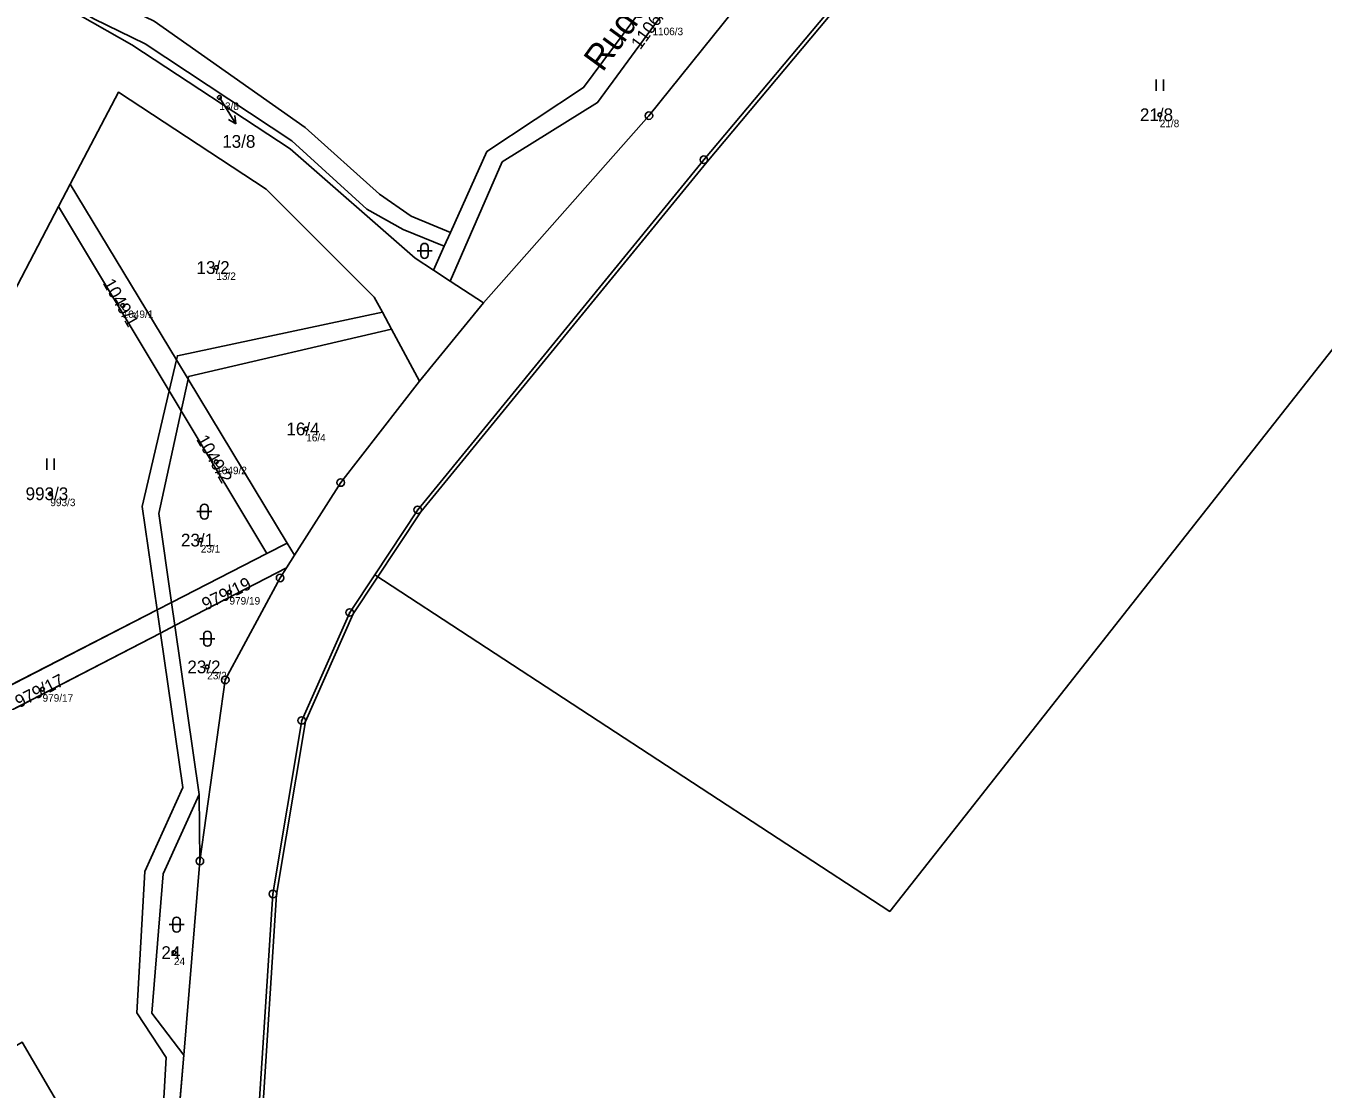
# Model space of a CAD drawing. Extents: x -554500 to -548272, y -1079733 to -1073730.
# Drawn here: x -553611.1 to -553438.1, y -1077094.1 to -1076952.3 of the extents above; entities that cross this region are included whole.
import ezdxf

# ---------------------------------------------------------------- set-up
doc = ezdxf.new("R2010")
doc.units = 0
for name, color, linetype in [('Definiční body', 7, 'Continuous'), ('Hranice parcel', 7, 'Continuous'), ('Parcelní čísla', 7, 'Continuous'), ('Polygon parcely', 7, 'Continuous'), ('Pop  PČ popisy', 7, 'Continuous'), ('Vnitřní kresba', 7, 'Continuous'), ('Značky bodu BP', 7, 'Continuous'), ('Značky kultur', 7, 'Continuous')]:
    doc.layers.add(name, color=color, linetype=linetype)

msp = doc.modelspace()

# ---------------------------------------------------------------- linework, layer by layer
at = {"layer": 'Definiční body'}
for centre in [(-553585.3, -1076961.86994), (-553459.84, -1076964.16994), (-553585.7, -1076984.53994), (-553598.2, -1076989.60994), (-553573.71, -1077006.05994), (-553585.72, -1077010.43994), (-553607.85, -1077014.69994), (-553587.78, -1077020.87994), (-553583.95, -1077027.81994), (-553586.92, -1077037.78994), (-553608.89, -1077040.76994), (-553591.36, -1077075.87994)]:
    msp.add_circle(centre, 0.25, dxfattribs=at)
at = {"layer": 'Hranice parcel'}
for p, q in [((-553606.76, -1076976.42), (-553605.2, -1076973.44)), ((-553605.2, -1076973.44), (-553591.03, -1076996.86)), ((-553591.99, -1077001), (-553606.76, -1076976.42)), ((-553555.3, -1076981.7), (-553554.47, -1076979.85)), ((-553556.73, -1076984.9), (-553555.3, -1076981.7)), ((-553556.73, -1076984.9), (-553554.51, -1076986.35)), ((-553554.51, -1076986.35), (-553550.08, -1076989.26)), ((-553550.08, -1076989.26), (-553558.58, -1076999.69)), ((-553562.32, -1076992.77), (-553563.55, -1076990.49)), ((-553558.58, -1076999.69), (-553562.32, -1076992.77)), ((-553591.03, -1076996.86), (-553591.99, -1077001)), ((-553590.4, -1077003.65), (-553589.48, -1076999.43)), ((-553589.48, -1076999.43), (-553576.25, -1077021.28)), ((-553578.96, -1077022.68), (-553590.4, -1077003.65)), ((-553591.67, -1077029.2), (-553578.96, -1077022.68)), ((-553576.25, -1077021.28), (-553578.96, -1077022.68)), ((-553576.25, -1077021.28), (-553575.27, -1077022.9)), ((-553575.27, -1077022.9), (-553576.34, -1077024.57)), ((-553576.34, -1077024.57), (-553591.23, -1077032.28)), ((-553591.23, -1077032.28), (-553591.67, -1077029.2)), ((-553593.59, -1077030.19), (-553620.08, -1077043.77)), ((-553593.15, -1077033.27), (-553593.59, -1077030.19)), ((-553591.23, -1077032.28), (-553587.99, -1077054.82)), ((-553619.77, -1077047.03), (-553593.15, -1077033.27)), ((-553587.99, -1077054.82), (-553587.9, -1077063.68)), ((-553590.06, -1077089.56), (-553587.9, -1077063.68)), ((-553590.06, -1077089.56), (-553590.84, -1077098.9))]:
    msp.add_line(p, q, dxfattribs=at)
for points in [[(-553564.57, -1077025.49), (-553558.84, -1077016.84), (-553520.67, -1076970.16), (-553501.33, -1076947.11), (-553465.45, -1076904.4), (-553423.27, -1076852.08)], [(-553554.47, -1076979.85), (-553549.63, -1076969.07), (-553536.72, -1076960.55), (-553519.57, -1076937.44), (-553521.21, -1076931.54), (-553518.95, -1076913.5), (-553514.27, -1076888.71)], [(-553512, -1076890.43), (-553517.05, -1076917.4), (-553518.54, -1076932.68), (-553517.07, -1076938.28), (-553534.84, -1076962.54), (-553547.59, -1076970.46), (-553554.51, -1076986.35)], [(-553550.08, -1076989.26), (-553527.99, -1076964.29), (-553506.71, -1076937.82), (-553488.91, -1076916.34)], [(-553375.59, -1076917.75), (-553495.86, -1077070.39), (-553564.57, -1077025.49)], [(-553603.86, -1076950.95), (-553596.97, -1076954.83), (-553575.87, -1076968.69), (-553559.18, -1076983.29), (-553556.73, -1076984.9)], [(-553555.3, -1076981.7), (-553560.76, -1076979.48), (-553565.63, -1076976.74), (-553575.63, -1076967.66), (-553595.19, -1076954.71), (-553602.06, -1076951.36), (-553603.34, -1076950.63)], [(-553594.01, -1076951.68), (-553573.86, -1076965.85), (-553563.94, -1076974.77), (-553559.73, -1076977.71), (-553554.47, -1076979.85)], [(-553563.55, -1076990.49), (-553564.64, -1076988.48), (-553579.07, -1076974.07), (-553598.77, -1076961.17), (-553605.2, -1076973.44)], [(-553606.76, -1076976.42), (-553615.57, -1076993.22), (-553617.38, -1076995.98)], [(-553591.03, -1076996.86), (-553590.9, -1076996.31), (-553563.55, -1076990.49)], [(-553562.32, -1076992.77), (-553589.4, -1076999.07), (-553589.48, -1076999.43)], [(-553575.27, -1077022.9), (-553569.11, -1077013.21), (-553558.58, -1076999.69)], [(-553593.59, -1077030.19), (-553595.58, -1077016.4), (-553591.99, -1077001)], [(-553590.4, -1077003.65), (-553593.37, -1077017.32), (-553591.67, -1077029.2)], [(-553587.9, -1077063.68), (-553584.51, -1077039.52), (-553577.2, -1077025.93), (-553576.34, -1077024.57)], [(-553582.46, -1077142.54), (-553581.94, -1077126.22), (-553578.15, -1077068.06), (-553574.31, -1077044.93), (-553567.91, -1077030.53), (-553564.57, -1077025.49)], [(-553592.83, -1077097.66), (-553592.42, -1077089.87), (-553596.33, -1077083.93), (-553595.23, -1077065.09), (-553590.17, -1077053.85), (-553593.15, -1077033.27)], [(-553587.99, -1077054.82), (-553592.82, -1077065.38), (-553594.31, -1077083.96), (-553590.06, -1077089.56)], [(-553616.83, -1077090.86), (-553611.6, -1077087.83), (-553603.97, -1077100.9), (-553613.39, -1077108.39), (-553617.19, -1077101.48)]]:
    msp.add_lwpolyline(points, dxfattribs=at)
at = {"layer": 'Polygon parcely'}
for points in [[(-553749.75, -1076835.17), (-553727.61, -1076858.33), (-553697.59, -1076889.73), (-553678.93, -1076907.98), (-553644.89, -1076926.99), (-553603.34, -1076950.63), (-553602.06, -1076951.36), (-553595.19, -1076954.71), (-553575.63, -1076967.66), (-553565.63, -1076976.74), (-553560.76, -1076979.48), (-553555.3, -1076981.7), (-553554.47, -1076979.85), (-553559.73, -1076977.71), (-553563.94, -1076974.77), (-553573.86, -1076965.85), (-553594.01, -1076951.68), (-553600.11, -1076948.7), (-553643.4, -1076924.53), (-553677.69, -1076904.94), (-553723.44, -1076855.84), (-553745.95, -1076831.68)], [(-553581.94, -1077126.22), (-553578.15, -1077068.06), (-553574.31, -1077044.93), (-553567.91, -1077030.53), (-553564.57, -1077025.49), (-553558.84, -1077016.84), (-553520.67, -1076970.16), (-553501.33, -1076947.11), (-553465.45, -1076904.4), (-553423.27, -1076852.08), (-553419.21, -1076844.97), (-553421.54, -1076842.38), (-553427.94, -1076836.45), (-553436.41, -1076852.84), (-553439.2, -1076856.37)], [(-553439.2, -1076856.37), (-553469.52, -1076891.6), (-553478.15, -1076902.37), (-553488.91, -1076916.34), (-553506.71, -1076937.82), (-553527.99, -1076964.29), (-553550.08, -1076989.26), (-553558.58, -1076999.69), (-553569.11, -1077013.21), (-553575.27, -1077022.9), (-553576.34, -1077024.57), (-553577.2, -1077025.93), (-553584.51, -1077039.52), (-553587.9, -1077063.68), (-553590.06, -1077089.56), (-553590.84, -1077098.9)], [(-553594.01, -1076951.68), (-553573.86, -1076965.85), (-553563.94, -1076974.77), (-553559.73, -1076977.71), (-553554.47, -1076979.85), (-553549.63, -1076969.07), (-553536.72, -1076960.55), (-553519.57, -1076937.44)], [(-553615.57, -1076993.22), (-553606.76, -1076976.42), (-553605.2, -1076973.44), (-553598.77, -1076961.17), (-553579.07, -1076974.07), (-553564.64, -1076988.48), (-553563.55, -1076990.49), (-553562.32, -1076992.77), (-553558.58, -1076999.69), (-553550.08, -1076989.26), (-553554.51, -1076986.35), (-553556.73, -1076984.9), (-553559.18, -1076983.29), (-553575.87, -1076968.69), (-553596.97, -1076954.83), (-553603.86, -1076950.95)], [(-553563.55, -1076990.49), (-553590.9, -1076996.31), (-553591.03, -1076996.86), (-553591.99, -1077001), (-553595.58, -1077016.4), (-553593.59, -1077030.19), (-553593.15, -1077033.27), (-553590.17, -1077053.85), (-553595.23, -1077065.09), (-553596.33, -1077083.93), (-553592.42, -1077089.87), (-553592.83, -1077097.66)], [(-553590.84, -1077098.9), (-553590.06, -1077089.56), (-553594.31, -1077083.96), (-553592.82, -1077065.38), (-553587.99, -1077054.82), (-553591.23, -1077032.28), (-553591.67, -1077029.2), (-553593.37, -1077017.32), (-553590.4, -1077003.65), (-553589.48, -1076999.43), (-553589.4, -1076999.07), (-553562.32, -1076992.77), (-553563.55, -1076990.49)], [(-553592.83, -1077097.66), (-553592.42, -1077089.87), (-553596.33, -1077083.93), (-553595.23, -1077065.09), (-553590.17, -1077053.85), (-553593.15, -1077033.27), (-553619.77, -1077047.03), (-553616.43, -1077078.95), (-553616.83, -1077090.86), (-553611.6, -1077087.83), (-553603.97, -1077100.9)]]:
    msp.add_lwpolyline(points, dxfattribs=at)
for points in [[(-553554.51, -1076986.35), (-553547.59, -1076970.46), (-553534.84, -1076962.54), (-553517.07, -1076938.28), (-553518.54, -1076932.68), (-553517.05, -1076917.4), (-553512, -1076890.43), (-553510.48, -1076882.29), (-553504.68, -1076861.59), (-553506.06, -1076851.89), (-553503.32, -1076846.84), (-553503.53, -1076843.36), (-553508.8, -1076852.27), (-553507.4, -1076860.92), (-553512.73, -1076880.52), (-553514.27, -1076888.71), (-553518.95, -1076913.5), (-553521.21, -1076931.54), (-553519.57, -1076937.44), (-553536.72, -1076960.55), (-553549.63, -1076969.07), (-553554.47, -1076979.85), (-553555.3, -1076981.7), (-553556.73, -1076984.9)], [(-553376.89, -1076853.97), (-553400.39, -1076850.62), (-553412.24, -1076848.14), (-553423.27, -1076852.08), (-553465.45, -1076904.4), (-553501.33, -1076947.11), (-553520.67, -1076970.16), (-553558.84, -1077016.84), (-553564.57, -1077025.49), (-553495.86, -1077070.39), (-553375.59, -1076917.75), (-553375.44, -1076901.76), (-553380.56, -1076888.59)], [(-553527.99, -1076964.29), (-553506.71, -1076937.82), (-553488.91, -1076916.34), (-553489.32, -1076910.33), (-553493.28, -1076903.6), (-553509.35, -1076891.3), (-553509.85, -1076892.07), (-553512, -1076890.43), (-553517.05, -1076917.4), (-553518.54, -1076932.68), (-553517.07, -1076938.28), (-553534.84, -1076962.54), (-553547.59, -1076970.46), (-553554.51, -1076986.35), (-553550.08, -1076989.26)], [(-553375.92, -1076952.27), (-553375.59, -1076917.75), (-553495.86, -1077070.39), (-553564.57, -1077025.49), (-553567.91, -1077030.53), (-553574.31, -1077044.93), (-553578.15, -1077068.06), (-553581.94, -1077126.22), (-553582.46, -1077142.54), (-553579.09, -1077159.81), (-553576.84, -1077210.2), (-553559.82, -1077228.21), (-553516.15, -1077228.13), (-553487.43, -1077239.1), (-553429.95, -1077188.53), (-553414.23, -1077141.95), (-553379.82, -1077166.37), (-553318.15, -1077137.23), (-553332.96, -1077096.33), (-553350.76, -1077002.12), (-553372.42, -1076964.83)], [(-553595.19, -1076954.71), (-553602.06, -1076951.36), (-553603.34, -1076950.63), (-553603.86, -1076950.95), (-553596.97, -1076954.83), (-553575.87, -1076968.69), (-553559.18, -1076983.29), (-553556.73, -1076984.9), (-553555.3, -1076981.7), (-553560.76, -1076979.48), (-553565.63, -1076976.74), (-553575.63, -1076967.66)], [(-553564.64, -1076988.48), (-553579.07, -1076974.07), (-553598.77, -1076961.17), (-553605.2, -1076973.44), (-553591.03, -1076996.86), (-553590.9, -1076996.31), (-553563.55, -1076990.49)], [(-553591.03, -1076996.86), (-553605.2, -1076973.44), (-553606.76, -1076976.42), (-553591.99, -1077001)], [(-553593.59, -1077030.19), (-553595.58, -1077016.4), (-553591.99, -1077001), (-553606.76, -1076976.42), (-553615.57, -1076993.22), (-553617.38, -1076995.98), (-553622.36, -1077026.98), (-553620.08, -1077043.77)], [(-553575.27, -1077022.9), (-553569.11, -1077013.21), (-553558.58, -1076999.69), (-553562.32, -1076992.77), (-553589.4, -1076999.07), (-553589.48, -1076999.43), (-553576.25, -1077021.28)], [(-553576.25, -1077021.28), (-553589.48, -1076999.43), (-553590.4, -1077003.65), (-553578.96, -1077022.68)], [(-553590.4, -1077003.65), (-553593.37, -1077017.32), (-553591.67, -1077029.2), (-553578.96, -1077022.68)], [(-553578.96, -1077022.68), (-553591.67, -1077029.2), (-553591.23, -1077032.28), (-553576.34, -1077024.57), (-553575.27, -1077022.9), (-553576.25, -1077021.28)], [(-553591.23, -1077032.28), (-553587.99, -1077054.82), (-553587.9, -1077063.68), (-553584.51, -1077039.52), (-553577.2, -1077025.93), (-553576.34, -1077024.57)], [(-553623.97, -1077049.21), (-553619.77, -1077047.03), (-553593.15, -1077033.27), (-553593.59, -1077030.19), (-553620.08, -1077043.77), (-553624.12, -1077045.87), (-553625.2, -1077046.42)], [(-553592.82, -1077065.38), (-553594.31, -1077083.96), (-553590.06, -1077089.56), (-553587.9, -1077063.68), (-553587.99, -1077054.82)], [(-553620.7, -1077095.09), (-553617.19, -1077101.48), (-553613.39, -1077108.39), (-553603.97, -1077100.9), (-553611.6, -1077087.83), (-553616.83, -1077090.86), (-553620.62, -1077093.06), (-553621.53, -1077093.58)]]:
    msp.add_lwpolyline(points, close=True, dxfattribs=at)
at = {"layer": 'Pop  PČ popisy'}
for p, q in [((-553585.3, -1076961.87), (-553584.71, -1076962.82)), ((-553584.71, -1076962.82), (-553583.12, -1076965.365)), ((-553583.12, -1076965.365), (-553584.075, -1076964.781)), ((-553583.12, -1076965.365), (-553583.226, -1076964.25))]:
    msp.add_line(p, q, dxfattribs=at)
at = {"layer": 'Vnitřní kresba'}
for p, q in [((-553520.28, -1076970.48), (-553500.95, -1076947.43)), ((-553558.42, -1077017.12), (-553520.28, -1076970.48)), ((-553589.48, -1076999.43), (-553591.03, -1076996.86)), ((-553590.4, -1077003.65), (-553591.99, -1077001)), ((-553558.42, -1077017.12), (-553567.45, -1077030.73)), ((-553593.59, -1077030.19), (-553591.67, -1077029.2)), ((-553567.45, -1077030.73), (-553573.83, -1077045.08)), ((-553593.15, -1077033.27), (-553591.23, -1077032.28)), ((-553573.83, -1077045.08), (-553577.66, -1077068.14)), ((-553581.44, -1077126.24), (-553577.66, -1077068.14))]:
    msp.add_line(p, q, dxfattribs=at)
at = {"layer": 'Značky bodu BP'}
for centre, radius in [((-553527.99, -1076964.28988), 0.5), ((-553527.99, -1076964.28988), 0.0303), ((-553520.67, -1076970.15988), 0.5), ((-553520.67, -1076970.15988), 0.0303), ((-553569.11, -1077013.20988), 0.5), ((-553569.11, -1077013.20988), 0.0303), ((-553558.84, -1077016.83988), 0.5), ((-553558.84, -1077016.83988), 0.0303), ((-553577.2, -1077025.92988), 0.5), ((-553577.2, -1077025.92988), 0.0303), ((-553567.91, -1077030.52988), 0.5), ((-553567.91, -1077030.52988), 0.0303), ((-553584.51, -1077039.51988), 0.5), ((-553584.51, -1077039.51988), 0.0303), ((-553574.31, -1077044.92988), 0.5), ((-553574.31, -1077044.92988), 0.0303), ((-553587.9, -1077063.67988), 0.5), ((-553587.9, -1077063.67988), 0.0303), ((-553578.15, -1077068.05988), 0.5), ((-553578.15, -1077068.05988), 0.0303)]:
    msp.add_circle(centre, radius, dxfattribs=at)
at = {"layer": 'Značky kultur'}
for p, q in [((-553460.331, -1076960.97), (-553460.331, -1076959.47)), ((-553459.33, -1076960.97), (-553459.33, -1076959.47)), ((-553558.931, -1076982.311), (-553556.929, -1076982.311)), ((-553558.431, -1076981.811), (-553558.431, -1076982.812)), ((-553557.429, -1076982.812), (-553557.429, -1076981.811)), ((-553608.331, -1077011.49), (-553608.331, -1077009.99)), ((-553607.33, -1077011.49), (-553607.33, -1077009.99)), ((-553588.301, -1077017.081), (-553586.299, -1077017.081)), ((-553587.801, -1077016.581), (-553587.801, -1077017.582)), ((-553586.799, -1077017.582), (-553586.799, -1077016.581)), ((-553587.891, -1077034.031), (-553585.889, -1077034.031)), ((-553587.391, -1077033.531), (-553587.391, -1077034.532)), ((-553586.389, -1077034.532), (-553586.389, -1077033.531)), ((-553592.011, -1077072.151), (-553590.009, -1077072.151)), ((-553591.511, -1077071.651), (-553591.511, -1077072.652)), ((-553590.509, -1077072.652), (-553590.509, -1077071.651))]:
    msp.add_line(p, q, dxfattribs=at)
for centre, start, end in [((-553557.93, -1076981.8109), 0, 180), ((-553557.93, -1076982.8109), 180, 359.9878861), ((-553587.3, -1077016.5809), 0, 180), ((-553587.3, -1077017.5809), 180, 359.9878861), ((-553586.89, -1077033.5309), 0, 180), ((-553586.89, -1077034.5309), 180, 359.9878861), ((-553591.01, -1077071.6509), 0, 180), ((-553591.01, -1077072.6509), 180, 359.9878861)]:
    msp.add_arc(centre, 0.5, start, end, dxfattribs=at)

# ---------------------------------------------------------------- texts
at = {"layer": 'Definiční body'}
for s, p in [('1106/3', (-553527.52, -1076953.556)), ('13/8', (-553585.3, -1076963.526)), ('21/8', (-553459.84, -1076965.826)), ('13/2', (-553585.7, -1076986.196)), ('1049/1', (-553598.2, -1076991.266)), ('16/4', (-553573.71, -1077007.716)), ('1049/2', (-553585.72, -1077012.096)), ('993/3', (-553607.85, -1077016.356)), ('23/1', (-553587.78, -1077022.536)), ('979/19', (-553583.95, -1077029.476)), ('23/2', (-553586.92, -1077039.446)), ('979/17', (-553608.89, -1077042.426)), ('24', (-553591.36, -1077077.536))]:
    msp.add_text(s, height=0.999996, dxfattribs=at).set_placement(p)
at = {"layer": 'Parcelní čísla'}
for s, rotation, p in [('1106/3', 54, (-553529.152, -1076955.593)), ('1049/1', 300, (-553600.909, -1076986.616)), ('1049/2', 300, (-553588.429, -1077007.446)), ('979/19', 26, (-553587.125, -1077030.314)), ('979/17', 27, (-553612.021, -1077043.319))]:
    msp.add_text(s, height=1.699998, rotation=rotation, dxfattribs=at).set_placement(p)
for s, p in [('21/8', (-553462.489, -1076965.02)), ('13/8', (-553584.92, -1076968.568)), ('13/2', (-553588.349, -1076985.39)), ('16/4', (-553576.359, -1077006.91)), ('993/3', (-553611.148, -1077015.55)), ('23/1', (-553590.429, -1077021.73)), ('23/2', (-553589.569, -1077038.64)), ('24', (-553593.036, -1077076.73))]:
    msp.add_text(s, height=1.699998, dxfattribs=at).set_placement(p)
at = {"layer": 'Pop  PČ popisy'}
msp.add_text('Rudoltický potok', height=3.399996, rotation=54, dxfattribs=at).set_placement((-553534.174, -1076958.579))

doc.saveas('drawing.dxf')
